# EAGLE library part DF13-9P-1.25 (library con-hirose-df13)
DF13-9P 1.25mm Pitch Miniature Crimping Connector.
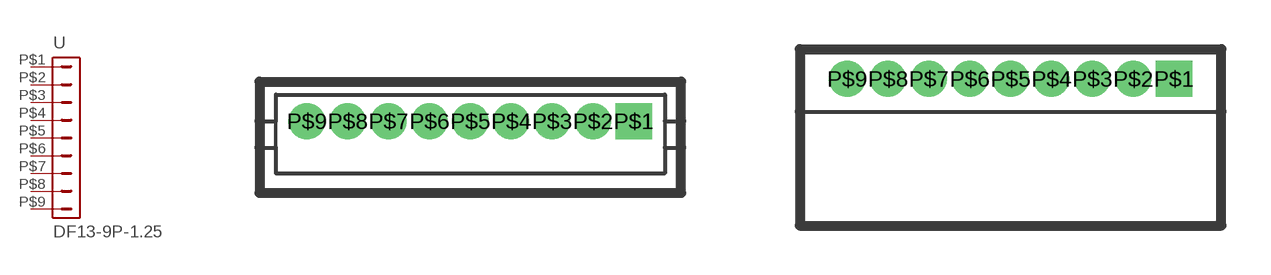
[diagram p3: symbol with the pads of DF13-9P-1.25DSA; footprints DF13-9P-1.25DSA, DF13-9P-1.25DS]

Designator prefix -

## DF13-9P-1.25DSA  [DF13-9P-1.25DSA]
P$1  1  pas
P$2  2  pas
P$3  3  pas
P$4  4  pas
P$5  5  pas
P$6  6  pas
P$7  7  pas
P$8  8  pas
P$9  9  pas

## DF13-9P-1.25DS  [DF13-9P-1.25DS]
Pads as for DF13-9P-1.25DSA

## DF13-9P-1.25V  [DF13C-9P-1.25V]
Pads as for DF13-9P-1.25DSA

## DF13-9P-1.25H  [DF13A-9P-1.25H]
Pads as for DF13-9P-1.25DSA

## Footprint DF13-9P-1.25DSA (pad centres in mm)
Single Row Straight Pin Header (Through hole)
drill 0.6 pad 1.016 square: P$1 5,0
drill 0.6 pad 1.016 round: P$2 3.75,0; P$3 2.5,0; P$4 1.25,0; P$5 0,0; P$6 -1.25,0; P$7 -2.5,0; P$8 -3.75,0; P$9 -5,0

## Footprint DF13-9P-1.25DS (pad centres in mm)
Single Row Right Angle Pin Header (Through hole)
drill 0.6 pad 1.016 square: P$1 5,0
drill 0.6 pad 1.016 round: P$2 3.75,0; P$3 2.5,0; P$4 1.25,0; P$5 0,0; P$6 -1.25,0; P$7 -2.5,0; P$8 -3.75,0; P$9 -5,0

## Footprint DF13C-9P-1.25V (pad centres in mm)
Single Row Straight Pin Header (SMT)
smd 1.6 x 2.2: M$0 7.45,-1.8; M$1 -7.45,-1.8
smd 0.7 x 1.8: P$1 -5,0.9; P$2 -3.75,0.9; P$3 -2.5,0.9; P$4 -1.25,0.9; P$5 0,0.9; P$6 1.25,0.9; P$7 2.5,0.9; P$8 3.75,0.9; P$9 5,0.9

## Footprint DF13A-9P-1.25H (pad centres in mm)
Single Row Straight Pin Header (SMT)
smd 1.6 x 2.2: M$0 -7.35,2.4; M$1 7.35,2.4
smd 0.7 x 1.8: P$1 -5,-0.9; P$2 -3.75,-0.9; P$3 -2.5,-0.9; P$4 -1.25,-0.9; P$5 0,-0.9; P$6 1.25,-0.9; P$7 2.5,-0.9; P$8 3.75,-0.9; P$9 5,-0.9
